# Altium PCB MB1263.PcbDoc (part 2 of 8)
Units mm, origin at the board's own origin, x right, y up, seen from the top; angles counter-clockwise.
Board outline 86 x 120 mm, 6 copper layers (Top Layer, Signal Layer 1, Signal Layer 2, Signal Layer 3, Signal Layer 4, Bottom Layer), stack 1.556 mm thick; 392 components, 421 nets, 1978 pads, 1444 vias.
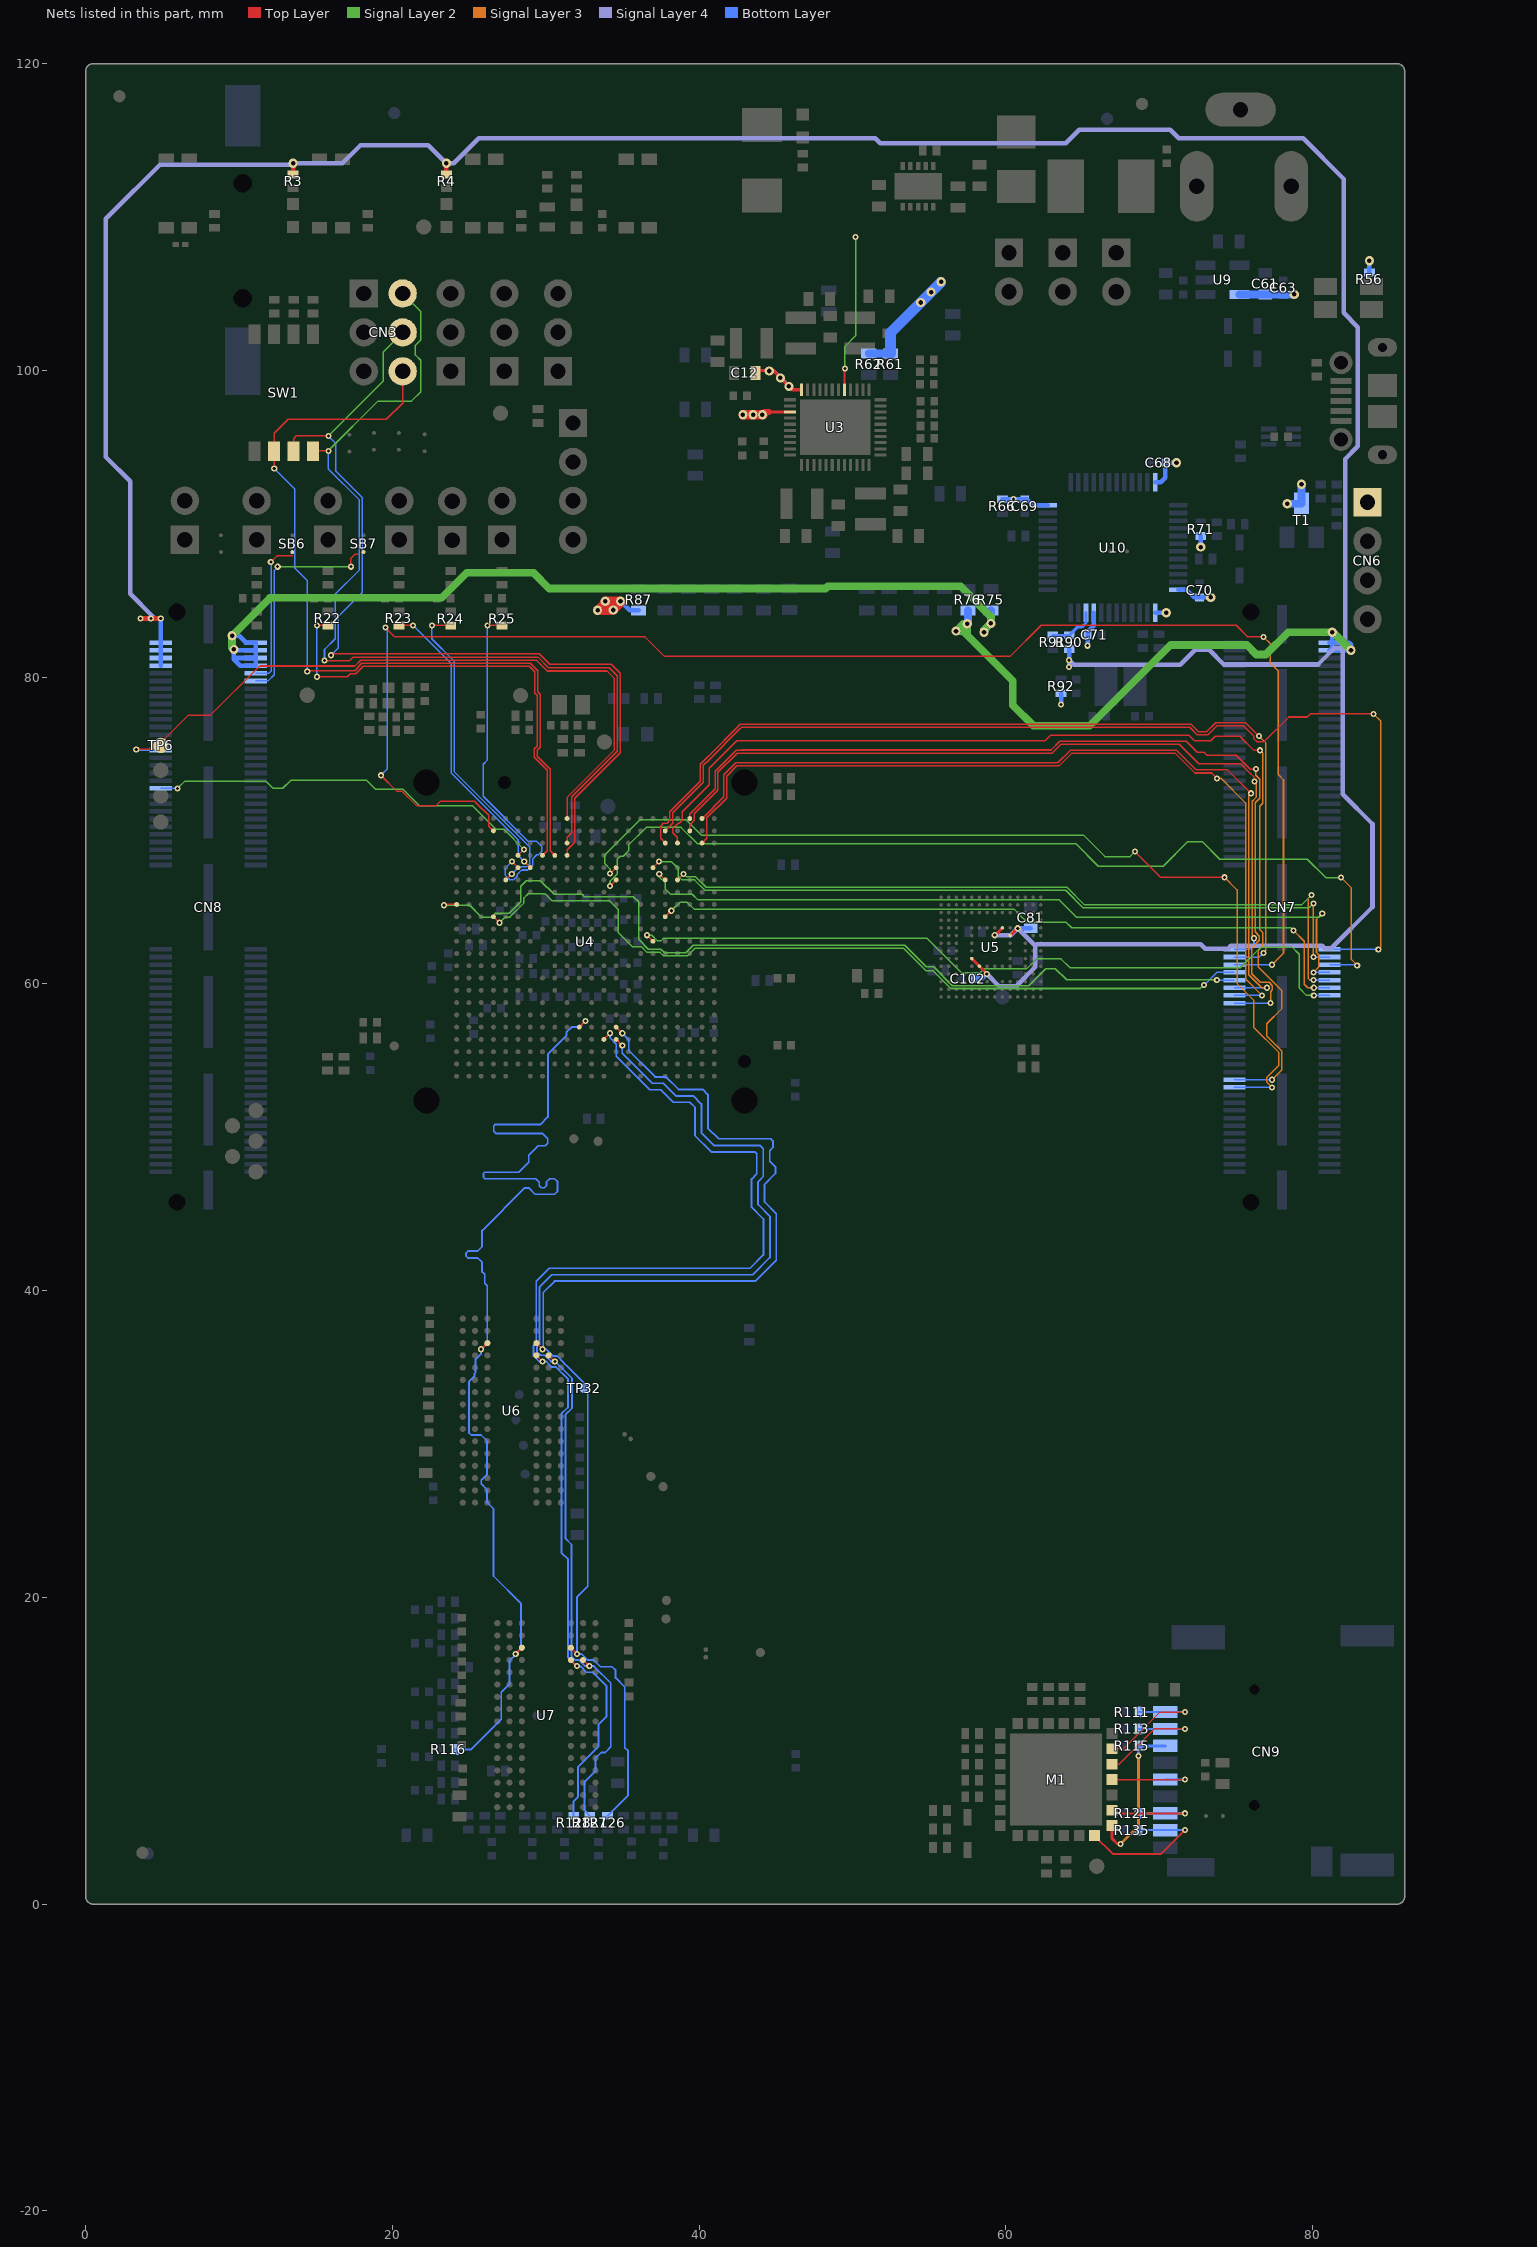
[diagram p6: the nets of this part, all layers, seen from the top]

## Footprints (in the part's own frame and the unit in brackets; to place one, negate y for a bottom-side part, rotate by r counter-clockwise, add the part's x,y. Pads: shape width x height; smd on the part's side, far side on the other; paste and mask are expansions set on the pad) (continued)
ICC_LFBGA448_18X18_STM32MP157BAA3_P080__SOCKET_IE_CS1627194MF [mm]
  round 0.32 smd mask+0.05: A1(-8.4,8.4) A2(-7.6,8.4) A3(-6.8,8.4) A4(-6,8.4) A5(-5.2,8.4) A6(-4.4,8.4) A7(-3.6,8.4) A8(-2.8,8.4) A9(-2,8.4) A10(-1.2,8.4) A11(-0.4,8.4) A12(0.4,8.4) A13(1.2,8.4) A14(2,8.4) A15(2.8,8.4) A16(3.6,8.4) A17(4.4,8.4) A18(5.2,8.4) A19(6,8.4) A20(6.8,8.4) A21(7.6,8.4) A22(8.4,8.4) AA1(-8.4,-7.6) AA2(-7.6,-7.6) AA3(-6.8,-7.6) AA4(-6,-7.6) AA5(-5.2,-7.6) AA6(-4.4,-7.6) AA7(-3.6,-7.6) AA8(-2.8,-7.6) AA9(-2,-7.6) AA10(-1.2,-7.6) AA11(-0.4,-7.6) AA12(0.4,-7.6) AA13(1.2,-7.6) AA14(2,-7.6) AA15(2.8,-7.6) AA16(3.6,-7.6) AA17(4.4,-7.6) AA18(5.2,-7.6) AA19(6,-7.6) AA20(6.8,-7.6) AA21(7.6,-7.6) AA22(8.4,-7.6) AB1(-8.4,-8.4) AB2(-7.6,-8.4) AB3(-6.8,-8.4) AB4(-6,-8.4) AB5(-5.2,-8.4) AB6(-4.4,-8.4) AB7(-3.6,-8.4) AB8(-2.8,-8.4) AB9(-2,-8.4) AB10(-1.2,-8.4) AB11(-0.4,-8.4) AB12(0.4,-8.4) AB13(1.2,-8.4) AB14(2,-8.4) AB15(2.8,-8.4) AB16(3.6,-8.4) AB17(4.4,-8.4) AB18(5.2,-8.4) AB19(6,-8.4) AB20(6.8,-8.4) AB21(7.6,-8.4) AB22(8.4,-8.4) B1(-8.4,7.6) B2(-7.6,7.6) B3(-6.8,7.6) B4(-6,7.6) B5(-5.2,7.6) B6(-4.4,7.6) B7(-3.6,7.6) B8(-2.8,7.6) B9(-2,7.6) B10(-1.2,7.6) B11(-0.4,7.6) B12(0.4,7.6) B13(1.2,7.6) B14(2,7.6) B15(2.8,7.6) B16(3.6,7.6) B17(4.4,7.6) B18(5.2,7.6) B19(6,7.6) B20(6.8,7.6) B21(7.6,7.6) B22(8.4,7.6) C1(-8.4,6.8) C2(-7.6,6.8) C3(-6.8,6.8) C4(-6,6.8) C5(-5.2,6.8) C6(-4.4,6.8) C7(-3.6,6.8) C8(-2.8,6.8) C9(-2,6.8) C10(-1.2,6.8) C11(-0.4,6.8) C12(0.4,6.8) C13(1.2,6.8) C14(2,6.8) C15(2.8,6.8) C16(3.6,6.8) C17(4.4,6.8) C18(5.2,6.8) C19(6,6.8) C20(6.8,6.8) C21(7.6,6.8) C22(8.4,6.8) D1(-8.4,6) D2(-7.6,6) D3(-6.8,6) D4(-6,6) D5(-5.2,6) D6(-4.4,6) D7(-3.6,6) D8(-2.8,6) D9(-2,6) D10(-1.2,6) D11(-0.4,6) D12(0.4,6) D13(1.2,6) D14(2,6) D15(2.8,6) D16(3.6,6) D17(4.4,6) D18(5.2,6) D19(6,6) D20(6.8,6) D21(7.6,6) D22(8.4,6) E1(-8.4,5.2) E2(-7.6,5.2) E3(-6.8,5.2) E4(-6,5.2) E5(-5.2,5.2) E6(-4.4,5.2) E7(-3.6,5.2) E8(-2.8,5.2) E9(-2,5.2) E10(-1.2,5.2) E11(-0.4,5.2) E12(0.4,5.2) E13(1.2,5.2) E14(2,5.2) E15(2.8,5.2) E16(3.6,5.2) E17(4.4,5.2) E18(5.2,5.2) E19(6,5.2) E20(6.8,5.2) E21(7.6,5.2) E22(8.4,5.2) F1(-8.4,4.4) F2(-7.6,4.4) F3(-6.8,4.4) F4(-6,4.4) F5(-5.2,4.4) F6(-4.4,4.4) F7(-3.6,4.4) F8(-2.8,4.4) F9(-2,4.4) F10(-1.2,4.4) F11(-0.4,4.4) F12(0.4,4.4) F13(1.2,4.4) F14(2,4.4) F15(2.8,4.4) F16(3.6,4.4) F17(4.4,4.4) F18(5.2,4.4) F19(6,4.4) F20(6.8,4.4) F21(7.6,4.4) G1(-8.4,3.6) G2(-7.6,3.6) G3(-6.8,3.6) G4(-6,3.6) G5(-5.2,3.6) G6(-4.4,3.6) G8(-2.8,3.6) G10(-1.2,3.6) G12(0.4,3.6) G14(2,3.6) G16(3.6,3.6) G17(4.4,3.6) G18(5.2,3.6) G19(6,3.6) G20(6.8,3.6) G21(7.6,3.6) G22(8.4,3.6) H1(-8.4,2.8) H2(-7.6,2.8) H3(-6.8,2.8) H4(-6,2.8) H5(-5.2,2.8) H6(-4.4,2.8) H7(-3.6,2.8) H9(-2,2.8) H11(-0.4,2.8) H13(1.2,2.8) H15(2.8,2.8) H17(4.4,2.8) H18(5.2,2.8) H19(6,2.8) H20(6.8,2.8) H21(7.6,2.8) H22(8.4,2.8) J1(-8.4,2) J2(-7.6,2) J3(-6.8,2) J4(-6,2) J5(-5.2,2) J6(-4.4,2) J8(-2.8,2) J9(-2,2) J10(-1.2,2) J11(-0.4,2) J12(0.4,2) J13(1.2,2) J14(2,2) J16(3.6,2) J17(4.4,2) J18(5.2,2) J19(6,2) J20(6.8,2) J21(7.6,2) K1(-8.4,1.2) K2(-7.6,1.2) K3(-6.8,1.2) K4(-6,1.2) K5(-5.2,1.2) K6(-4.4,1.2) K7(-3.6,1.2) K9(-2,1.2) K10(-1.2,1.2) K11(-0.4,1.2) K12(0.4,1.2) K13(1.2,1.2) K14(2,1.2) K15(2.8,1.2) K17(4.4,1.2) K18(5.2,1.2) K19(6,1.2) K20(6.8,1.2) K21(7.6,1.2) K22(8.4,1.2) L1(-8.4,0.4) L2(-7.6,0.4) L3(-6.8,0.4) L4(-6,0.4) L5(-5.2,0.4) L6(-4.4,0.4) L8(-2.8,0.4) L9(-2,0.4) L10(-1.2,0.4) L11(-0.4,0.4) L12(0.4,0.4) L13(1.2,0.4) L14(2,0.4) L16(3.6,0.4) L17(4.4,0.4) L18(5.2,0.4) L19(6,0.4) L20(6.8,0.4) L21(7.6,0.4) L22(8.4,0.4) M1(-8.4,-0.4) M2(-7.6,-0.4) M3(-6.8,-0.4) M4(-6,-0.4) M5(-5.2,-0.4) M6(-4.4,-0.4) M7(-3.6,-0.4) M9(-2,-0.4) M10(-1.2,-0.4) M11(-0.4,-0.4) M12(0.4,-0.4) M13(1.2,-0.4) M14(2,-0.4) M15(2.8,-0.4) M17(4.4,-0.4) M18(5.2,-0.4) M19(6,-0.4) M20(6.8,-0.4) M21(7.6,-0.4) M22(8.4,-0.4) N1(-8.4,-1.2) N2(-7.6,-1.2) N3(-6.8,-1.2) N4(-6,-1.2) N5(-5.2,-1.2) N6(-4.4,-1.2) N8(-2.8,-1.2) N9(-2,-1.2) N10(-1.2,-1.2) N11(-0.4,-1.2) N12(0.4,-1.2) N13(1.2,-1.2) N14(2,-1.2) N16(3.6,-1.2) N17(4.4,-1.2) N18(5.2,-1.2) N19(6,-1.2) N20(6.8,-1.2) N21(7.6,-1.2) N22(8.4,-1.2) P1(-8.4,-2) P2(-7.6,-2) P3(-6.8,-2) P4(-6,-2) P5(-5.2,-2) P6(-4.4,-2) P7(-3.6,-2) P9(-2,-2) P10(-1.2,-2) P11(-0.4,-2) P12(0.4,-2) P13(1.2,-2) P14(2,-2) P15(2.8,-2) P17(4.4,-2) P18(5.2,-2) P19(6,-2) P20(6.8,-2) P21(7.6,-2) R1(-8.4,-2.8) R2(-7.6,-2.8) R3(-6.8,-2.8) R4(-6,-2.8) R5(-5.2,-2.8) R6(-4.4,-2.8) R8(-2.8,-2.8) R10(-1.2,-2.8) R12(0.4,-2.8) R14(2,-2.8) R16(3.6,-2.8) R17(4.4,-2.8) R18(5.2,-2.8) R19(6,-2.8) R20(6.8,-2.8) R21(7.6,-2.8) R22(8.4,-2.8) T1(-8.4,-3.6) T2(-7.6,-3.6) T3(-6.8,-3.6) T4(-6,-3.6) T5(-5.2,-3.6) T6(-4.4,-3.6) T7(-3.6,-3.6) T9(-2,-3.6) T11(-0.4,-3.6) T13(1.2,-3.6) T15(2.8,-3.6) T17(4.4,-3.6) T18(5.2,-3.6) T19(6,-3.6) T20(6.8,-3.6) T21(7.6,-3.6) T22(8.4,-3.6) U1(-8.4,-4.4) U2(-7.6,-4.4) U3(-6.8,-4.4) U4(-6,-4.4) U5(-5.2,-4.4) U6(-4.4,-4.4) U7(-3.6,-4.4) U8(-2.8,-4.4) U9(-2,-4.4) U10(-1.2,-4.4) U11(-0.4,-4.4) U12(0.4,-4.4) U13(1.2,-4.4) U14(2,-4.4) U15(2.8,-4.4) U16(3.6,-4.4) U17(4.4,-4.4) U18(5.2,-4.4) U19(6,-4.4) U20(6.8,-4.4) U21(7.6,-4.4) V1(-8.4,-5.2) V2(-7.6,-5.2) V3(-6.8,-5.2) V4(-6,-5.2) V5(-5.2,-5.2) V6(-4.4,-5.2) V7(-3.6,-5.2) V8(-2.8,-5.2) V9(-2,-5.2) V10(-1.2,-5.2) V11(-0.4,-5.2) V12(0.4,-5.2) V13(1.2,-5.2) V14(2,-5.2) V15(2.8,-5.2) V16(3.6,-5.2) V17(4.4,-5.2) V18(5.2,-5.2) V19(6,-5.2) V20(6.8,-5.2) V21(7.6,-5.2) V22(8.4,-5.2) W1(-8.4,-6) W2(-7.6,-6) W3(-6.8,-6) W4(-6,-6) W5(-5.2,-6) W6(-4.4,-6) W7(-3.6,-6) W8(-2.8,-6) W9(-2,-6) W10(-1.2,-6) W11(-0.4,-6) W12(0.4,-6) W13(1.2,-6) W14(2,-6) W15(2.8,-6) W16(3.6,-6) W17(4.4,-6) W18(5.2,-6) W19(6,-6) W20(6.8,-6) W21(7.6,-6) W22(8.4,-6) Y1(-8.4,-6.8) Y2(-7.6,-6.8) Y3(-6.8,-6.8) Y4(-6,-6.8) Y5(-5.2,-6.8) Y6(-4.4,-6.8) Y7(-3.6,-6.8) Y8(-2.8,-6.8) Y9(-2,-6.8) Y10(-1.2,-6.8) Y11(-0.4,-6.8) Y12(0.4,-6.8) Y13(1.2,-6.8) Y14(2,-6.8) Y15(2.8,-6.8) Y16(3.6,-6.8) Y17(4.4,-6.8) Y18(5.2,-6.8) Y19(6,-6.8) Y20(6.8,-6.8) Y21(7.6,-6.8) Y22(8.4,-6.8)
  round 0.5 hole 1.7 unplated mask+0.05: NPTH1(-10.737,10.362) NPTH2(9.987,10.362) NPTH3(-10.737,-10.362) NPTH4(9.987,-10.362)
  round 0.5 hole 0.85 unplated mask+0.05: NPTH5(-10.737,-5.282) NPTH6(7.447,10.362)
  silkscreen extent -12.12,-11.61 11.24,11.75, body extent -13.14,-12.76 12.39,12.76, height 10.18
ICC_LQFP48_7X7_P050 [mm]
  rect 0.3x1.2 smd mask+0.05: 1(-2.75,-4.25) 2(-2.25,-4.25) 3(-1.75,-4.25) 4(-1.25,-4.25) 5(-0.75,-4.25) 6(-0.25,-4.25) 7(0.25,-4.25) 8(0.75,-4.25) 9(1.25,-4.25) 10(1.75,-4.25) 11(2.25,-4.25) 12(2.75,-4.25) 25(2.75,4.25) 26(2.25,4.25) 27(1.75,4.25) 28(1.25,4.25) 29(0.75,4.25) 30(0.25,4.25) 31(-0.25,4.25) 32(-0.75,4.25) 33(-1.25,4.25) 34(-1.75,4.25) 35(-2.25,4.25) 36(-2.75,4.25)
  rect 1.2x0.3 smd mask+0.05: 13(4.25,-2.75) 14(4.25,-2.25) 15(4.25,-1.75) 16(4.25,-1.25) 17(4.25,-0.75) 18(4.25,-0.25) 19(4.25,0.25) 20(4.25,0.75) 21(4.25,1.25) 22(4.25,1.75) 23(4.25,2.25) 24(4.25,2.75) 37(-4.25,2.75) 38(-4.25,2.25) 39(-4.25,1.75) 40(-4.25,1.25) 41(-4.25,0.75) 42(-4.25,0.25) 43(-4.25,-0.25) 44(-4.25,-0.75) 45(-4.25,-1.25) 46(-4.25,-1.75) 47(-4.25,-2.25) 48(-4.25,-2.75)
  silkscreen extent -3.52,-3.52 3.52,3.52, body extent -4.5,-4.5 4.5,4.5, height 1.6
ICC_P-WFBGA153_13X11P5_P050 [mm]
  round 0.23 smd mask+0.05: A1(-3.25,-3.25) A2(-3.25,-2.75) A3(-3.25,-2.25) A4(-3.25,-1.75) A5(-3.25,-1.25) A6(-3.25,-0.75) A7(-3.25,-0.25) A8(-3.25,0.25) A9(-3.25,0.75) A10(-3.25,1.25) A11(-3.25,1.75) A12(-3.25,2.25) A13(-3.25,2.75) A14(-3.25,3.25) B1(-2.75,-3.25) B2(-2.75,-2.75) B3(-2.75,-2.25) B4(-2.75,-1.75) B5(-2.75,-1.25) B6(-2.75,-0.75) B7(-2.75,-0.25) B8(-2.75,0.25) B9(-2.75,0.75) B10(-2.75,1.25) B11(-2.75,1.75) B12(-2.75,2.25) B13(-2.75,2.75) B14(-2.75,3.25) C1(-2.25,-3.25) C2(-2.25,-2.75) C3(-2.25,-2.25) C4(-2.25,-1.75) C5(-2.25,-1.25) C6(-2.25,-0.75) C7(-2.25,-0.25) C8(-2.25,0.25) C9(-2.25,0.75) C10(-2.25,1.25) C11(-2.25,1.75) C12(-2.25,2.25) C13(-2.25,2.75) C14(-2.25,3.25) D1(-1.75,-3.25) D2(-1.75,-2.75) D3(-1.75,-2.25) D4(-1.75,-1.75) D12(-1.75,2.25) D13(-1.75,2.75) D14(-1.75,3.25) E1(-1.25,-3.25) E2(-1.25,-2.75) E3(-1.25,-2.25) E5(-1.25,-1.25) E6(-1.25,-0.75) E7(-1.25,-0.25) E8(-1.25,0.25) E9(-1.25,0.75) E10(-1.25,1.25) E12(-1.25,2.25) E13(-1.25,2.75) E14(-1.25,3.25) F1(-0.75,-3.25) F2(-0.75,-2.75) F3(-0.75,-2.25) F5(-0.75,-1.25) F10(-0.75,1.25) F12(-0.75,2.25) F13(-0.75,2.75) F14(-0.75,3.25) G1(-0.25,-3.25) G2(-0.25,-2.75) G3(-0.25,-2.25) G5(-0.25,-1.25) G10(-0.25,1.25) G12(-0.25,2.25) G13(-0.25,2.75) G14(-0.25,3.25) H1(0.25,-3.25) H2(0.25,-2.75) H3(0.25,-2.25) H5(0.25,-1.25) H10(0.25,1.25) H12(0.25,2.25) H13(0.25,2.75) H14(0.25,3.25) J1(0.75,-3.25) J2(0.75,-2.75) J3(0.75,-2.25) J5(0.75,-1.25) J10(0.75,1.25) J12(0.75,2.25) J13(0.75,2.75) J14(0.75,3.25) K1(1.25,-3.25) K2(1.25,-2.75) K3(1.25,-2.25) K5(1.25,-1.25) K6(1.25,-0.75) K7(1.25,-0.25) K8(1.25,0.25) K9(1.25,0.75) K10(1.25,1.25) K12(1.25,2.25) K13(1.25,2.75) K14(1.25,3.25) L1(1.75,-3.25) L2(1.75,-2.75) L3(1.75,-2.25) L12(1.75,2.25) L13(1.75,2.75) L14(1.75,3.25) M1(2.25,-3.25) M2(2.25,-2.75) M3(2.25,-2.25) M4(2.25,-1.75) M5(2.25,-1.25) M6(2.25,-0.75) M7(2.25,-0.25) M8(2.25,0.25) M9(2.25,0.75) M10(2.25,1.25) M11(2.25,1.75) M12(2.25,2.25) M13(2.25,2.75) M14(2.25,3.25) N1(2.75,-3.25) N2(2.75,-2.75) N3(2.75,-2.25) N4(2.75,-1.75) N5(2.75,-1.25) N6(2.75,-0.75) N7(2.75,-0.25) N8(2.75,0.25) N9(2.75,0.75) N10(2.75,1.25) N11(2.75,1.75) N12(2.75,2.25) N13(2.75,2.75) N14(2.75,3.25) P1(3.25,-3.25) P2(3.25,-2.75) P3(3.25,-2.25) P4(3.25,-1.75) P5(3.25,-1.25) P6(3.25,-0.75) P7(3.25,-0.25) P8(3.25,0.25) P9(3.25,0.75) P10(3.25,1.25) P11(3.25,1.75) P12(3.25,2.25) P13(3.25,2.75) P14(3.25,3.25)
  silkscreen extent -6.78,-6.02 6.63,5.87, body extent -6.55,-5.8 6.55,5.8, height 1
ICC_WFQFN44-EPAD_5X6_P040 [mm]
  rect 0.8x0.2 smd mask+0.05: 1(-2.45,2.2) 2(-2.45,1.8) 3(-2.45,1.4) 4(-2.45,1) 5(-2.45,0.6) 6(-2.45,0.2) 7(-2.45,-0.2) 8(-2.45,-0.6) 9(-2.45,-1) 10(-2.45,-1.4) 11(-2.45,-1.8) 12(-2.45,-2.2) 23(2.45,-2.2) 24(2.45,-1.8) 25(2.45,-1.4) 26(2.45,-1) 27(2.45,-0.6) 28(2.45,-0.2) 29(2.45,0.2) 30(2.45,0.6) 31(2.45,1) 32(2.45,1.4) 33(2.45,1.8) 34(2.45,2.2)
  rect 0.2x0.8 smd mask+0.05: 13(-1.8,-2.95) 14(-1.4,-2.95) 15(-1,-2.95) 16(-0.6,-2.95) 17(-0.2,-2.95) 18(0.2,-2.95) 19(0.6,-2.95) 20(1,-2.95) 21(1.4,-2.95) 22(1.8,-2.95) 35(1.8,2.95) 36(1.4,2.95) 37(1,2.95) 38(0.6,2.95) 39(0.2,2.95) 40(-0.2,2.95) 41(-0.6,2.95) 42(-1,2.95) 43(-1.4,2.95) 44(-1.8,2.95)
  rect 3.6x4.6 smd paste-1.8 mask+0.05: ep(0,0)
  silkscreen extent -2.5,-3 2.5,3, body extent -2.5,-3 2.5,3, height 0.81
IND_2520_TOKO_DFE252012P [mm]
  rect 0.8x2 smd mask+0.05: 1(-1,0) 2(1,0)
  silkscreen extent -1.35,-1.12 1.35,1.12, body extent -1.35,-1.1 1.35,1.1, height 2
L0603 [mm]
  rect 0.8x0.95 smd mask+0.05: 1(-0.8,0) 2(0.8,0)
  silkscreen extent -1.33,-0.6 1.33,0.6, body extent -0.87,-0.47 0.87,0.47, height 0.95
LED_0603_GREEN [mm]
  rect 0.8x0.8 smd mask+0.05: 1(-0.75,0) 2(0.75,0)
  silkscreen extent -0.25,-0.4 1.25,0.4, body extent -0.8,-0.4 0.8,0.4, height 0.6
LED_0603_ORANGE_H0P4 [mm]
  rect 0.8x0.8 smd mask+0.05: 1(-0.75,0) 2(0.75,0)
  silkscreen extent -0.25,-0.4 1.25,0.4, body extent -0.8,-0.4 0.79,0.4, height 0.4
LED_0603_RED [mm]
  rect 0.8x0.8 smd mask+0.05: 1(-0.75,0) 2(0.75,0)
  silkscreen extent -0.25,-0.4 1.25,0.4, body extent -0.8,-0.4 0.8,0.4, height 0.6
LED_0603_SMD-B_BLUE_H0P4 [mm]
  rect 0.6x1 smd mask+0.05: 1(-0.65,0) 2(0.65,0)
  silkscreen extent -0.23,-0.45 1.07,0.45, body extent -0.85,-0.45 0.85,0.45, height 0.5
LED_BI-GR_HSMF-A201-A00J1 [mm]
  rect 1.1x1.5 smd mask+0.05: 1(-0.75,-1.5) 2(-0.75,1.5) 3(0.75,1.5) 4(0.75,-1.5)
  silkscreen extent -1.65,-1.85 1.65,1.85, body extent -1.5,-1.85 1.5,1.85, height 2.1
LINK200 [mm]
  rect 0.2x0.35 on Mid4 mask+0.05: 1(0,-0.225) 2(0,0.225)
MIRE_PLACE_SMD_0P8MM [mm]
  round 0.8 smd paste-10 mask+0.2: 1(0,0)
  Top Layer keep-out circle w0.01: c0,0 r0.804
MOD_SD-CARD_8X8_MB1256 [mm] "MB1256"
  rect 0.7x0.7 smd mask+0.05: 1(-3.65,3) 2(-3.65,2) 3(-3.65,1) 4(-3.65,0) 5(-3.65,-1) 6(-3.65,-2) 7(-3.65,-3) 8(-2.5,-3.65) 9(-1.5,-3.65) 10(-0.5,-3.65) 11(0.5,-3.65) 12(1.5,-3.65) 13(2.5,-3.65) 14(3.65,-3) 15(3.65,-2) 16(3.65,-1) 17(3.65,0) 18(3.65,1) 19(3.65,2) 20(3.65,3) 21(2.5,3.65) 22(1.5,3.65) 23(0.5,3.65) 24(-0.5,3.65) 25(-1.5,3.65) 26(-2.5,3.65)
  rect 6x6 smd mask+0.05: 27(0,0)
  silkscreen extent -4,-4 4,4, body extent -4,-4 4,4, height 1.4
NPN_SOT23 [mm]
  rect 1x1.4 smd mask+0.05: 1(-0.95,-1.1) 2(0.95,-1.1) 3(0,1.1)
  silkscreen extent -1.63,-0.82 1.63,0.82, body extent -1.56,-1.25 1.56,1.25, height 1.1
PTC_BEL-FUSE_1812_0ZCG0260FF2C [mm]
  rect 2.4x3.5 smd mask+0.05: 1(-2.3,0) 2(2.3,0)
  silkscreen extent -1,-1.73 1,1.73, body extent -2.36,-1.71 2.36,1.71, height 1.2
R0402 [mm]
  rect 0.51x0.7 smd mask+0.05: 1(-0.45,0) 2(0.45,0)
  silkscreen extent 0,-0.3 0,0.3, body extent -0.52,-0.3 0.52,0.3, height 0.4
R0603 [mm]
  rect 0.64x1 smd mask+0.05: 1(-0.7,0) 2(0.7,0)
  silkscreen extent -1.05,-0.58 1.05,0.58, body extent -0.9,-0.5 0.9,0.5, height 0.56
REG_SOT23-5L [mm]
  rect 0.6x1.3 smd mask+0.05: 1(-0.95,-1.1) 2(0,-1.1) 3(0.95,-1.1) 4(0.95,1.1) 5(-0.95,1.1)
  silkscreen extent -1.6,-0.95 1.6,0.97, body extent -1.52,-1.25 1.52,1.25, height 1.1
SOLDER-BRIDGE_R0603-0R [mil]
  round 10 smd paste-393.7: 1(-19.68,0) 2(23.62,0)
  Top Layer region: -5.91,19.68 13.78,0 -5.91,-19.69 47.24,-19.69 47.24,19.68 -5.91,19.68
  Top Layer region: -47.24,-19.69 -47.24,19.68 -15.75,19.68 3.94,0 -15.75,-19.69 -47.24,-19.69
  silkscreen extent -50,-23 50,23, body extent -36,-20 36,20, height 22
SWI_CTS_CTS218-4LP [mm] "GULL WING TERMINAL"
  rect 0.76x1.27 smd mask+0.05: 1(-1.905,-3.81) 2(-0.635,-3.81) 3(0.635,-3.81) 4(1.905,-3.81) 5(1.905,3.81) 6(0.635,3.81) 7(-0.635,3.81) 8(-1.905,3.81)
  silkscreen extent -3.13,-3.05 3.13,3.05, body extent -3.18,-4.32 3.18,4.32, height 2.85
SWI_JIUBABA_C-TS-02H-2-5-B-V-T_R_BLUE [mm] "BLUE"
  rect 0.75x1 smd mask+0.05: 1(-2.225,0.75) 2(2.225,0.75) 3(-2.225,-0.75) 4(2.225,-0.75)
  silkscreen extent -1.85,-1.6 1.85,1.6, body extent -2.45,-1.6 2.45,1.6, height 2.6
SWI_JIUBABA_C-TS-02H-2-5-K-V-T_R_BLACK [mm] "BLACK"
  rect 0.75x1 smd mask+0.05: 1(-2.225,0.75) 2(2.225,0.75) 3(-2.225,-0.75) 4(2.225,-0.75)
  silkscreen extent -1.85,-1.6 1.85,1.6, body extent -2.45,-1.6 2.45,1.6, height 2.6
TP_SMD_0-3MM [mm]
  round 0.3 smd paste-10 mask+0.05: 1(0,0)
  silkscreen extent -0.3,-0.3 0.3,0.3
TP_SMD_0-6MM [mm]
  round 0.6 smd paste-10 mask+0.05: 1(0,0)
  silkscreen extent -0.5,-0.5 0.5,0.5
TP_SMD_1MM [mm]
  round 1 smd paste-10 mask+0.05: 1(0,0)
  silkscreen extent -0.7,-0.7 0.7,0.7

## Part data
B1: "TS-02H SMD Light Touch Switch black", Manuf_1=Jiubaba, Manuf_Part_1="C-TS-02H-2.5-K-V-T/R BLACK"
B2 B3 B4: "TS-02H SMD Light Touch Switch blue", Manuf_1=Jiubaba, Manuf_Part_1="C-TS-02H-2.5-K-V-T/R BLUE"
BT1: "Battery  holder xcfbattery XCF-12", Manuf_1=xcfbattery, Manuf_Part_1=XCF-12
C1: library part Cap_220uF_POL_10%_TAJA, "Polarized Capacitor,220uF,10V,10%,AVX", Manuf_1=AVX, Manuf_Part_1=TAJC227K010R
C2 C18 C28 C29 C30 C31 C32 C34 C38 C40 C41 C44 C45 C46 C47 C49 C50 C51 C52 C53 C54 C58 C63 C64 C65 C66 C68 C69 C70 C71 C72 C75 C92 C97 C102 C113 C115 C116 C117 C118 C119 C120 C121 C123 C124 C125 C126 C127 C128 C129 C131 C132 C135 C136 C137 C138 C139 C140: library part Cap_100nF_X7R_10%_0402, "Capacitor,100nF,16V,X7R,10%,0402,YAGEO", Manuf_1=YAGEO, Manuf_Part_1=CC0402KRX7R7BB104
C3 C4 C55 C61 C62 C76: library part Cap_1uF_X5R_10%_0603, "Capacitor,1uF,16V,X5R,10%,0603,YAGEO", Manuf_1=YAGEO, Manuf_Part_1=CC0603KRX5R7BB105
C5 C300: library part Cap_10nF_X7R_10%_0402, "Capacitor,10nF,16V,X7R,10%,0402,YAGEO", Manuf_1=YAGEO, Manuf_Part_1=CC0402KRX7R7BB103
C6 C7 C12 C26 C27 C133 C134: library part Cap_22uF_X5R_20%_0603_MURATA, "Capacitor MLCC 22µF 20% 6,3V 7,5µF@3,3V ESR=4mohm@100kHz  Z=5mohm@2MHz X5R 0603", Manuf_1=MURATA, Manuf_Part_1=GRM188R60J226MEA0J
C8 C9 C10 C22 C23 C24 C25: library part Cap_10uF_X5R_10%_0603_MURATA, "Capacitor MLCC 10µF 10% 10V 2,5µF@5,5V Z=5mohm@2MHz X5R 0603", Manuf_1=MURATA, Manuf_Part_1=GRM188R61A106KE69D
C11 C13 C14 C15 C17 C20 C21: library part Cap_4.7uF_X5R_20%_6V3_0402, "Capacitor MLCC 4,7µF 20% 6,3V 1,9uF@3,3V X5R 0402", Manuf_1=MURATA, Manuf_Part_1=GRM155R60J475ME47
C16 C19 C42 C43 C67 C77 C78 C79 C80 C82 C83 C84 C85 C86 C87 C88 C89 C90 C91 C93 C94 C96 C98 C99 C100 C101 C103 C104 C105 C106 C109 C110 C111 C112 C114: library part Cap_1uF_X5R_10%_6V3_0402, "Capacitor MLCC 1µF 10% 6,3V 0,4uF@3,3V X5R 0402 MURATA", Manuf_1=MURATA, Manuf_Part_1=GRM155R61E105KA12
C33 C35 C36 C37: library part Cap_6.8pF_NPO_0402, "Capacitor, MLCC, 6.8pF, 50V, NPO, +-0.25pF, 0402, T=0.5mm", Manuf_1=YAGEO, Manuf_Part_1=CC0402CRNPO9BN6R8, Package=C0402
C39 C81 C95: library part Cap_2.2uF_X5R_10%_0603, "Capacitor,2.2uF,10V, X5R,10%,0603,YAGEO", Manuf_1=YAGEO, Manuf_2=KEMET, Manuf_Part_1=CC0603KRX5R6BB225, Manuf_Part_2=C0603C225K8PACTU
C48 C59 C122 C130: library part Cap_10uF_X5R_10%_0603, "Capacitor,10uF,6.3V,X5R,10%,0603,YAGEO", Manuf_1=YAGEO, Manuf_Part_1=CC0603KRX5R5BB106
C56: library part Cap_100pF_NPO_5%_0402, "Capacitor,100pF,50V,NPO,5%,0402,YAGEO", Manuf_1=YAGEO, Manuf_Part_1=CC0402JRNPO9BN101
C57: library part Cap_4.7uF_X5R_20%_0603_16V_MURATA, "Capacitor MLCC 4,7uF 20% 16V 3uF@5V ESR=6mohm@100kHz  Z=20mohm@2MHz X5R 0603", Manuf_1=MURATA, Manuf_Part_1=GRM188R61C475MAAJ
C60: library part Cap_10nF_X7R_10%_0603, "Capacitor,10nF,50V,X7R,10%,0603,YAGEO", Manuf_1=YAGEO, Manuf_Part_1=CC0603KRX7R9BB103
C73 C74: library part Cap_10pF_NPO_5%_0402, "Capacitor,10pF,50V,NPO,5%,0402,YAGEO", Manuf_1=YAGEO, Manuf_Part_1=CC0402JRNPO9BN100
C107 C108: library part Cap_1nF_X7R_10%_0402, "Capacitor,1nF,16V,X7R,10%,0402,YAGEO", Manuf_1=YAGEO, Manuf_Part_1=CC0402KRX7R7BB102
CN1: library part CONN_Power_DC10B, "DC Power Jack 2.5mm 5A Right Angle through hole", Manuf_1=CLIFF, Manuf_Part_1=DC-10B
CN2: library part "Header 2 pins", "Header 2 pins", Manuf_1=SAMTEC, Manuf_2=KONTEC, Manuf_Part_1=TSW-102-07-x-S, Manuf_Part_2=4711955140470
CN3: library part MCD-00233, "Header, 3x2, 2,54mm, VR, TH, Height 5.84mm/2.54mm", Manufacturer=SAMTEC, Manufacturer_Part_Number=TSW-103-07-x-D
CN4: "USB-MICRO-B, 1050170001, SMT, MOLEX", Manuf_1=MOLEX
CN5 CN6: library part "Header 4", "Header, 4-Pin", Manuf_1=Samtec, Manuf_Part_1=TSW-104-07-x-S
CN7 CN8: "Samtec connector QTH 120p", Manuf_1=SAMTEC
CN9: library part microSD-PJS008-2003, "Memory Card Connectors MicroSD Card Conn Revrs Mnt Push-Push", Manuf_1=YAMAICHI
D1: library part SMAJ5.0A-TR, "Transil unidirectional diode Vrm=5.0V, Vbr=6.4V(10mA), Vcl=13.4V(174A), SMA", Manuf_1=STM
D2 D3 D4 D5: Manuf_1=STM
F1: library part 0ZCG0260FF2C, "SMD, PTC resettable fuse, IH:2.6A, IT:5A, Vdc_max:8V, Rmax:47mohm, BELFUSE", Manuf_1=BELFUSE
JP1 JP2 JP6 JP7 JP8 JP9 JP10 JP11: library part TSW-102-07-x-S, "Connector jumper 1 position", Manuf_1=SAMTEC, Manuf_2=KONTEC, Manuf_Part_2=4711955140470
JP3 JP4 JP5: library part "Header 3", "Header, 3-Pin", Manuf_1=Samtec, Manuf_Part_1=TSW-103-07-F-S
L1 L2 L3 L4 L5: library part IND_1uH_42mohm_3.2A, "SMD power inductor. 1µH, 3,2A, 42mohm, 2,5x2,0x1,2mm", Manuf_1=Murata, Manuf_Part_1=DFE252012P-1R0M{}P2
LD1 LD3: "LED, Green, 0603", Manuf_1=EVERLIGHT, Manuf_Part_1=19-213SYGC/S530-E2/TR8
LD2: "LED, Red, 0603", Manuf_1=EVERLIGHT, Manuf_Part_1=19-213-R6C-AP1Q2B/3T
LD4: "LED, Orange, 0603", Manuf_1=EVERLIGHT, Manuf_Part_1=19-217/S2C-AM2N2VY/3T, Package="LED 0603"
LD5: "LED Blue, 0603 SMD, Forward Voltage Min=2,8V, Max=3,1V", Manuf_1=EVERLIGHT, Manuf_Part_1=19-217-BHC-ZL1M2RY-3T
LD6: "Bicolor Led", Manuf_1="Avago Technologies", Manuf_2=everluck, Manuf_Part_1=HSMF-A201-A00J1, Manuf_Part_2=LE-RGW35280
LE1: library part "IND_4.7uH 600mohm_80mA_0603", "IND 4.7µH 20% 80mA 600mhom 0603", Manuf_1=MURATA, Manuf_Part_1=LQM18FN4R7M00D
LNK1 LNK2: "link 0.2mm"
M1: "SDcard3.0 dual voltage level  translator", Manuf_1=STM, Manuf_Part_1=MB1256
R1: library part Res_39_1%_0402, "Resistor,39R,0402,1%,YAGEO", Manuf_1=YAGEO, Manuf_Part_1=RC0402FR-0739RL
R2 R4 R57 R58: library part Res_330_1%_0402, "Resistor,330R,0402,1%,YAGEO", Manuf_1=YAGEO, Manuf_Part_1=RC0402FR-07330RL
R3 R11 R12 R13 R66 R303: library part Res_1K_1%_0402, "Resistor,1K,0402,1%,YAGEO", Manuf_1=YAGEO, Manuf_Part_1=RC0402FR-071KL
R5 R6: "Resistor,680R,0402,1%,1/16W", Manuf_1=YAGEO, Manuf_Part_1=RC0402FR-07680RL, Package=R0402
R7 R50 R59 R60 R61 R62 R63 R64 R68 R72 R75 R76 R77 R78 R79 R80 R81 R82 R83 R84 R85 R86 R87: library part Res_0_ULO_0603, "Resistor,0R,0603,ULO,ROHM", Manuf_1=ROHM, Manuf_Part_1=PMR03EZPJ000
R8 R33 R37 R38 R39 R40 R41 R43 R44 R46 R47 R48 R49 R52 R88 R89 R97 R100 R103 R108 R111 R113 R115 R121 R135 R302 R900 R901: library part Res_10K_1%_0402, "Resistor,10K,0402,1%,YAGEO", Manuf_1=YAGEO, Manuf_Part_1=RC0402FR-0710KL
R9 R10 R67 R118: library part Res_100_1%_0402, "Resistor,100R,0402,1%,YAGEO", Manuf_1=YAGEO, Manuf_Part_1=RC0402FR-07100RL
R14 R73 R74 R92: library part Res_100K_1%_0402, "Resistor,100K,0402,1%,YAGEO", Manuf_1=YAGEO, Manuf_Part_1=RC0402FR-07100KL, Manuf_Part_2=RT0402FRE07100KL
R15 R16 R17 R18 R19 R20 R21 R22 R23 R24 R25 R26 R27 R28 R29 R42 R45 R54 R56 R71 R94 R95 R96 R98 R99 R101: library part Res_0_5%_0402, "Resistor,0R,0402,5%,YAGEO", Manuf_1=YAGEO, Manuf_Part_1=RC0402JR-070RL
R30 R31 R34 R35 R51 R53 R93: library part Res_1K5_1%_0402, "Resistor,1K5,0402,1%,YAGEO", Manuf_1=YAGEO, Manuf_Part_1=RC0402FR-071K5L
R32: library part Res_3K_1%_0402, "Resistor,3K,0402,1%,YAGEO", Manuf_1=YAGEO, Manuf_Part_1=RC0402FR-073KL
R36 R55 R102: library part Res_240_1%_0402, "Resistor,240R,0402,1%,YAGEO", Manuf_1=YAGEO, Manuf_Part_1=RC0402FR-07240RL
R65: library part Res_36K_1%_0402, "Resistor,36K,0402,1%,YAGEO", Manuf_1=YAGEO, Manuf_Part_1=RC0402FR-0736KL
R69 R90 R91: library part Res_4K7_1%_0402, "Resistor,4K7,0402,1%,YAGEO", Manuf_1=YAGEO, Manuf_Part_1=RC0402FR-074K7L, Manuf_Part_2=RT0402FRE074K7L
R70: library part Res_2K7_1%_0402, "Resistor,2K7,0402,1%,YAGEO", Manuf_1=YAGEO, Manuf_Part_1=RC0402FR-072K7L
R104 R105 R106 R107 R109 R110 R112 R114 R116 R117 R119 R120 R122 R123 R124 R125 R126 R127 R128 R129 R130 R131 R132 R133 R134: library part Res_56_1%_0402, "Resistor,56R,0402,1%,YAGEO", Manuf_1=YAGEO, Manuf_Part_1=RC0402FR-0756RL
R300: library part Res_10R_1%_0402, "Resistor,10R,0402,1%,1/16W", Manuf_1=YAGEO, Manuf_Part_1=RC0402FR-0710RL
SB1 SB4 SB5 SB6 SB7 SB8 SB9: "Solder Bridge ON"
SB2 SB3: "Solder Bridge OFF"
SW1: library part SWITCH_4WAY, "Quad SPST surface mount switch. 1.27mm pitch. Tinned legs.", Manuf_1=CTS
T1: library part 9013-SOT23_1, "NPN Bipolar Transistor", Manuf_1=NXP
TP1 TP2 TP3 TP4 TP5 TP6 TP7 TP8 TP9 TP13 TP14 TP15 TP18 TP19 TP29 TP30 TP31: library part "TP 1mm", "Test Point"
TP12 TP16 TP17 TP22 TP23 TP24 TP25 TP26 TP32 TP33 TP34 TP35 TP36 TP37: library part "TP 0.6mm", "Test Point"
TP20 TP21 TP27 TP28: library part "TP 0.3mm", "Test Point"
U1: "Electronic fuse for 5V line, 3.6A max, DFN10(3x3mm)", Manuf_1=STM
U2: "ESD protection 6V1", Manuf_1=STMICROELECTRONICS
U3: "PMIC WFQFN 5.0x6.0x0.8 44L 0.4 pitch", Manuf_1=ST, Manuf_Part_1=STPMU1APQR
U4: "MPU LFBGA18x18 with crypto", Manuf_1=ST, Manuf_Part_1=STM32MP157CAA3
U5: library part eMMC_THGBMNG5D1LBAIL, "eMMC 4GB 153 Balls WFBGA 15nm", Manuf_1=TOSHIBA
U6: "DDR3L, 16 bits, 4Gb, NANYA, 20nm", Manuf_1=NANYA, Manuf_Part_1=NT5CC256M16ER-EK
U7: "DDR3L, 16 bits, 4Gb, NANYA, 20nm", Manuf_1=NANYA
U8: "USB ESD protection", Manuf_1=ST
U9: "Ultra low drop-low noise BiCMOS voltage, regulators low ESR capacitors compatible", Manuf_1=STM
U10: "Medium-density performance line ARM-based 32-bit MCU with 128KB Flash", Manuf_1=STM
X2: library part XTAL_32K_NX2012SA, "Crystal 32.768kHz, 12.5pF, +/-20ppm@25°C; -0.04ppm/°C² ; ESRmax :70Kohm", Manuf_1=NDK, Manuf_Part_1="NX2012SA 32.768kHz EXS00A-MU00528"
X3: library part XTAL_8M_NX3225GD, "Crystal 8Mhz, 8pF, -+50PPM, SMD", Manuf_1=NDK, Manuf_Part_1="NX3225GD 8MHz EXS00A-CG04874"
X6: "Oscillator 24Mhz, +-50ppm, Vcc:3.3V typ (1.62V min), square wave: [0.1Vcc;0.9Vcc], Enable pin", Manuf_1=NDK, Manuf_Part_1="NZ2016SH 24MHz END4869F"

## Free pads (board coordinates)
  round 0.508 on Mech16: 1(18.738,-18.015) 1(67.585,-18.015)

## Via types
v1: diameter 0.4, hole 0.2, Top Layer to Bottom Layer, tented both sides, 771 vias
v2: diameter 0.6, hole 0.3, Top Layer to Bottom Layer, tented both sides, 670 vias
v3: diameter 0.4, hole 0.2, Top Layer to Bottom Layer, 3 vias

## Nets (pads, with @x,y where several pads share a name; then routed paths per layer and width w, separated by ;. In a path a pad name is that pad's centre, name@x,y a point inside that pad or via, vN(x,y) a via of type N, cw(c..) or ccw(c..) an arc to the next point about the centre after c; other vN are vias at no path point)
1V8: CN7.2 CN7.4 R76.2 | length 40.7
  Signal Layer 2 w0.5: v2(82.5,81.75) 81.325,82.925 v2(81.275,82.925) 78.4,82.925 76.95,81.475 76.322,81.475 75.697,82.1 70.75,82.1 65.475,76.825 61.8,76.825 60.45,78.175 60.45,79.75 57.475,82.725 ; 57.475,82.725 57.2,83 v2(56.75,83) 57.225,83.475 v2(57.475,83.475) 57.475,82.725
  Bottom Layer w0.3: CN7.2@81.1,82.25 CN7.2@81.275,82.25 ; v2(81.275,82.925) CN7.2@81.275,82.25 ; CN7.2@81.275,82.25 81.275,81.925 CN7.4@81.1,81.75 v2(82.5,81.75) 82.5,82.125 82.375,82.25 CN7.2@81.275,82.25
  Bottom Layer w0.5: v2(56.75,83) 57,83 v2(57.475,83.475) 57.527,83.527 R76.2@57.527,84.35
2V8: CN8.2 CN8.4 CN8.6 CN8.8 R75.2 | length 65.6
  Signal Layer 2 w0.5: v2(9.669,81.806) 9.55,81.925 v2(9.55,82.7) 12.025,85.175 23.225,85.175 24.85,86.8 29.2,86.8 30.225,85.775 48.244,85.775 48.394,85.925 57.05,85.925 59.025,83.95 v2(59.025,83.5) 58.575,83.05 v2(58.575,82.925)
  Bottom Layer w0.3: 9.669,81.156 9.763,81.25 CN8.6@11.1,81.25 ; 9.669,81.156 v2(9.669,81.806) ; 9.669,81.156 10.075,80.75 CN8.8@11.1,80.75 CN8.6@11.1,81.25 ; v2(9.669,81.806) 9.725,81.75 CN8.4@11.1,81.75 ; v2(9.669,81.806) 9.669,82.581 v2(9.55,82.7) 10.025,82.7 10.475,82.25 CN8.2@11.1,82.25 CN8.4@11.1,81.75 ; CN8.6@11.1,81.25 CN8.4@11.1,81.75
  Bottom Layer w0.5: v2(58.575,82.925) 58.575,83.05 v2(59.025,83.5) v2(59.025,83.5) R75.2@59.027,84.35
3V3: C81.1 C102.2 CN8.1 CN8.3 CN8.5 CN8.7 R3.1 R4.2 R61.1 R62.1 R87.2 R90.1 U3.27 U5.E6 U5.F5 U5.J10 U5.K9 | length 249.5
  Top Layer w0.1: U3.27@49.479,98.736 49.479,100.104 v1(49.5,100.125)
  Top Layer w0.2: U5.E6@57.8,61.625 U5.F5@58.275,61.15 58.75,60.675 v1(58.75,60.65) ; v1(59.275,63.175) 59.3,63.175 U5.J10@59.775,63.65 ; U5.K9@60.275,63.15 60.75,63.625 v1(60.775,63.625)
  Top Layer w0.3: v1(3.575,83.825) v1(4.25,83.825) ; v1@4.275,83.85 v1(4.25,83.825) ; v1(4.9,83.825) v1(4.25,83.825) ; R3.1@13.525,112.775 v2(13.525,113.5) ; R4.2@23.525,112.775 v2(23.525,113.5)
  Top Layer w0.6: v2(33.381,84.356) 33.875,84.356 34.381,84.356 v2(34.4,84.375) 34.875,84.85 v2(34.875,84.95) 34.4,84.95 v2(33.875,84.95) 33.875,84.85 v2(33.381,84.356)
  Signal Layer 2 w0.1: v1(49.5,100.125) 49.5,101.558 49.504,101.554 50.2,102.25 v1(50.2,108.7)
  Signal Layer 2 w0.3: v1@49.496,100.046 49.5,100.05 v1(49.5,100.125)
  Signal Layer 4 w0.3: v1(4.9,83.825) 4.5,83.825 4.375,83.95 2.9,85.425 2.9,92.775 1.325,94.35 1.325,109.875 1.65,110.2 4.85,113.4 13.425,113.4 v2(13.525,113.5) 16.75,113.5 17.925,114.675 22.35,114.675 v2(23.525,113.5) 24,113.5 25.625,115.125 51.493,115.125 51.818,114.8 63.9,114.8 64.775,115.675 70.728,115.675 71.278,115.125 79.375,115.125 82.025,112.475 82.025,103.747 82.95,102.822 82.95,95.044 82.125,94.219 82.125,82.303 81.95,82.128 81.95,81.9 ; v1(58.75,60.65) 59.55,59.85 60.675,59.85 61.925,61.1 61.925,62.475 ; v1(59.275,63.175) 60.325,63.175 v1(60.775,63.625) 61.925,62.475 ; v1(64.125,81.1) 64.35,80.875 64.425,80.8 71.364,80.8 72.339,81.775 73.253,81.775 74.203,80.825 80.35,80.825 81.425,81.9 81.95,81.9 ; 61.925,62.475 62.025,62.575 72.714,62.575 72.989,62.3 74.486,62.3 74.661,62.475 80.625,62.475 80.775,62.325 81.211,62.325 83.9,65.014 83.9,70.425 81.95,72.375 81.95,81.9
  Bottom Layer w0.3: v1(3.575,83.825) v1(4.25,83.825) v1(4.9,83.825) CN8.1@4.9,82.25 CN8.3@4.9,81.75 CN8.5@4.9,81.25 CN8.7@4.9,80.75 ; v2(34.875,84.95) 35.469,84.356 R87.2@36.052,84.356 ; C102.2@57.95,60.35 58.45,60.35 v1(58.75,60.65) ; v1(59.275,63.175) v1@59.3,63.175 ; v1(60.775,63.625) C81.1@61.625,63.625 ; v1(64.125,80.65) v1(64.125,81.1) R90.1@64.125,81.825
  Bottom Layer w0.5: R62.1@51.05,101.1 R61.1@52.475,101.1
  Bottom Layer w0.7: R61.1@52.475,101.1 52.475,102.45 v2(54.45,104.425) v2(55.125,105.1) 55.75,105.725 v2@55.75,105.75
  other v2: 55.775,105.775
3V3_ST_LINK: C61.1 C63.2 C68.2 C69.2 C70.2 C71.2 CN6.1 R56.1 R66.1 R71.1 R92.2 T1.3 U9.5 U10.1 U10.9 U10.24 U10.36 U10.48 | length 19
  Bottom Layer w0.3: R66.1@59.775,91.6 v1(60.5,91.6) C69.2@61.225,91.6 61.375,91.6 61.775,91.2 U10.24@62.725,91.2 ; v1(63.6,78.225) R92.2@63.6,78.95 ; v1(65.325,82.05) C71.2@65.325,82.775 65.325,82.95 65.725,83.35 U10.9@65.725,84.2 ; U10.1@69.725,84.2 v2(70.45,84.2) ; U10.36@69.725,92.7 70.1,92.7 70.4,93 C68.2@70.4,93.975 v2(71.125,93.975) ; U10.48@71.225,85.7 71.775,85.7 72.275,85.2 C70.2@72.625,85.2 v2(73.35,85.2) ; v2(72.7,88.475) R71.1@72.7,89.2 ; R56.1@83.7,106.375 v2(83.7,107.15)
  Bottom Layer w0.5: U9.5@75.225,104.95 C61.1@76.9,104.95 C63.2@78.075,104.95 v2(78.8,104.95) ; v2(78.35,91.3) 79.25,91.3 T1.3@79.275,91.325 v2(79.275,92.575)
ADC118_DAC1: R24.1 U4.V6 | length 21.4
  Top Layer w0.1: v1(22.575,83.375) 23.795,83.375 R24.1@23.8,83.37 ; U4.V6@27.39,66.78 v1@27.779,67.17
  Bottom Layer w0.1: v1(22.575,83.375) 22.575,82.5 24.025,81.05 24.025,73.845 28.95,68.92 28.95,67.83 28.745,67.625 28.24,67.625 v1(27.785,67.17)
ADC119_DAC2: R25.1 U4.U5 | length 22.9
  Top Layer w0.1: v1(26.2,83.375) 27.145,83.375 R25.1@27.15,83.37 ; v1@27.8,67.97 U4.U5@28.19,67.58
  Bottom Layer w0.1: v1(26.2,83.375) 26.2,74.6 25.925,74.325 25.925,72.228 28.851,69.301 29.399,69.301 29.735,68.965 29.735,68.625 29.53,68.42 29.42,68.42 29.15,68.15 29.15,67.747 28.828,67.425 28.425,67.425 28.135,67.135 28.135,67.025 27.9,66.79 27.66,66.79 27.35,67.1 27.35,67.525 v1(27.8,67.975)
AIN_1: R90.2 R91.2 U10.10 | length 3.2
  Bottom Layer w0.2: R91.2@63.05,82.725 R90.2@64.125,82.725 64.675,83.275 64.975,83.275 65.225,83.525 U10.10@65.225,84.2
ANA0: R22.1 U4.R4 | length 31.3
  Top Layer w0.09: v1(15.075,80.025) 17.045,80.025 17.25,80.23 17.611,80.23 18.091,80.71 27.352,80.71 28.921,80.71 29.29,80.341 29.29,78.962 29.44,78.812 29.44,75.509 29.248,75.316 29.248,74.773 30.095,73.925 30.095,68.685 U4.R4@29.79,68.38 ; v1(15.075,83.375) R22.1@15.8,83.375
  Bottom Layer w0.1: v1(15.075,80.025) v1(15.075,83.375)
ANA0_MB: CN8.10 SB6.2 | length 9.8
  Top Layer w0.1: v1(12.075,87.5) 12.475,87.9 13.5,87.9
  Bottom Layer w0.1: CN8.10@11.1,80.25 11.95,80.25 12.1,80.4 12.1,87.475 v1(12.075,87.5)
ANA1: R23.1 U4.T5 | length 19.9
  Top Layer w0.1: R23.1@20.425,83.375 v1(21.35,83.375) ; v1@28.6,67.97 U4.T5@28.99,67.58
  Bottom Layer w0.1: v1(21.35,83.375) 23.825,80.9 23.825,73.762 28.2,69.387 28.2,68.375 v1(28.6,67.975)
ANA1_MB: CN8.12 SB7.2 | length 14.4
  Top Layer w0.1: v1(17.3,87.2) 17.3,87.75 17.55,88 17.75,88
  Signal Layer 2 w0.1: v1(12.525,87.2) v1(17.3,87.2)
  Bottom Layer w0.1: CN8.12@11.1,79.75 11.9,79.75 12.3,80.15 12.3,86.95 12.525,87.175 v1(12.525,87.2)
ANTI_TAMP2: CN8.29 TP6.1 U4.N1 | length 46.1
  Top Layer w0.1: v1(3.3,75.279) 3.321,75.3 4.475,75.3 4.812,75.637 6.7,77.525 8.15,77.525 11.35,80.725 17.562,80.725 17.932,81.095 29.405,81.095 30.1,80.4 33.986,80.4 34.475,79.911 34.475,75.245 31.39,72.16 U4.N1@31.39,70.78
  Bottom Layer w0.1: v1(3.3,75.279) 3.329,75.25 CN8.29@4.9,75.25
BOOT0: CN3.2 SW1.8 U4.N3 | length 63.3
  Top Layer w0.09: SW1.8@14.825,94.725 14.853,94.753 v1(15.825,94.753) ; U4.N3@31.39,69.18 31.39,69.548 31.695,69.853 31.695,72.189 34.67,75.164 34.67,80.086 34.156,80.6 33.9,80.6
  Top Layer w0.1: v1(15.576,81.079) 15.58,81.075 17.209,81.075 17.443,81.309 29.491,81.309 30.2,80.6 33.9,80.6
  Signal Layer 2 w0.1: v1(15.825,94.753) 19.072,98 21.255,98 21.845,98.59 21.845,100.655 21.5,101 21.5,101.643 21.845,101.988 21.845,103.84 CN3.2@20.67,105.015
  Bottom Layer w0.1: v1@15.575,81.05 v1@15.575,81.079 ; v1@15.576,81.051 v1(15.576,81.079) 15.576,81.801 16.275,82.5 16.275,85.411 17.85,86.986 17.85,91.55 15.825,93.575 v1(15.825,94.753)
BOOT1: CN3.4 SW1.7 U4.N4 | length 60.7
  Top Layer w0.09: SW1.7@13.555,94.725 13.555,95.555 13.725,95.725 v1(15.825,95.725) ; v1(16,81.425) 16.11,81.535 29.565,81.535 30.269,80.831 33.964,80.831 ; U4.N4@31.39,68.38 31.39,68.748 31.885,69.243 31.885,72.11 34.86,75.085 34.86,80.252 34.282,80.83 33.964,80.83
  Signal Layer 2 w0.1: v1(15.825,95.725) 19.4,99.3 19.4,101.205 CN3.4@20.67,102.475
  Bottom Layer w0.1: v1(15.825,95.725) 16.3,95.25 16.3,93.45 18.05,91.7 18.05,85.533 16.475,83.958 16.475,81.9 v1(16,81.425)
BOOT2: CN3.6 SW1.6 U4.P4 | length 55.8
  Top Layer w0.09: v1(12.3,93.6) 12.285,93.615 SW1.6@12.285,94.725 12.285,95.885 13.2,96.8 19.6,96.8 20.7,97.9 20.67,97.93 CN3.6@20.67,99.935 ; v1(14.45,80.375) 14.495,80.42 17.533,80.42 18.013,80.9 27.431,80.9 29,80.9 29.48,80.42 29.48,79.041 29.63,78.891 29.63,75.43 29.438,75.238 29.438,74.851 30.285,74.004 30.285,68.685 U4.P4@30.59,68.38
  Bottom Layer w0.1: v1(12.3,93.6) 13.65,92.25 13.65,87.1 14.45,86.3 v1(14.45,80.375)
BST_OUT: C12.2 U3.34 U3.37 | length 10.3
  Top Layer w0.2: C12.2@43.7,99.825 43.875,100 44.577,100 44.825,100 45.31,99.515 45.325,99.5 45.325,99.475 45.848,98.952 46.064,98.736 U3.34@46.679,98.736 ; 44.545,97.286 U3.37@45.929,97.286
  Top Layer w0.3: v2@43.388,97.236 v2(43.518,97.106) ; v2@44.052,97.106 v2(44.124,97.106) ; v2@44.124,97.034 44.209,96.949 44.245,96.985 44.545,97.286
  Top Layer w0.4: v2@44.232,97.286 44.545,97.286
  Top Layer w0.6: v2(42.852,97.106) v2(43.518,97.106) v2@44.052,97.106
  Signal Layer 4 w0.2: v2@42.775,97.125 42.823,97.077 42.825,97.075 42.852,97.075 43.518,97.075 v2@43.971,97.075 ; v2(44.577,99.956) 44.894,99.956 45.323,99.527 45.873,98.977 45.875,98.975 45.875,98.956 v2@45.875,98.95
  other v2: 45.852,98.956 45.302,99.506
CAN1_RX: CN7.97 U4.J5 | length 63.2
  Top Layer w0.1: v1@34.2,67.19 U4.J5@34.59,67.58 ; v1(68.425,68.625) 68.425,68.618 70.098,66.945 74.245,66.945 v1(74.25,66.95)
  Signal Layer 2 w0.1: v1(34.195,67.19) 34.195,67.495 33.845,67.845 33.845,68.395 33.95,68.5 33.95,68.503 36.147,70.7 39.143,70.7 40.143,69.7 65.058,69.7 66.458,68.3 68.1,68.3 v1(68.425,68.625)
  Signal Layer 3 w0.1: v1(74.25,66.95) 75.075,66.125 75.075,60.017 76.15,58.942 76.15,57.172 77.8,55.522 77.8,54.695 77,53.895 77,53.6 v1(77.35,53.25)
  Bottom Layer w0.1: CN7.97@74.9,53.25 v1(77.35,53.25)
CAN1_TX: CN7.95 U4.D3 | length 69.6
  Top Layer w0.09: U4.D3@38.59,69.18 38.59,69.548 38.285,69.853 38.285,70.133 38.627,70.475 38.716,70.475 38.895,70.653 38.895,71.222 40.655,72.982 40.655,74.051 42.179,75.575 42.454,75.85 42.7,75.85
  Top Layer w0.1: 42.7,75.85 62.55,75.85 62.925,76.225 71.919,76.225 72.294,75.85 73.351,75.85 73.651,76.15 75.245,76.15 76.17,75.225 76.575,75.225 v1(76.579,75.229)
  Signal Layer 2 w0.1: v1(76.579,75.229) v1@76.654,75.229
  Signal Layer 3 w0.1: v1(76.579,75.229) 76.75,75.057 76.75,71.775 76.55,71.575 76.55,63.55 76.75,63.35 76.75,62.47 76.45,62.17 76.45,61.103 78,59.553 78,58.395 77,57.395 77,56.605 78,55.605 78,54.4 v1(77.35,53.75)
  Bottom Layer w0.1: CN7.95@74.9,53.75 v1(77.35,53.75)
CAN_FD_STBY: CN8.39 U4.U4 | length 26.7
  Top Layer w0.1: U4.U4@28.19,68.38 v1@28.58,68.77
  Signal Layer 2 w0.1: v1(6,72.75) 6.45,73.2 11.775,73.2 12.225,72.75 12.85,72.75 13.384,73.284 18.309,73.284 18.917,72.675 20.708,72.675 21.758,71.625 25.212,71.625 26.762,70.075 27.28,70.075 v1(28.585,68.77)
  Bottom Layer w0.1: CN8.39@4.9,72.75 v1(6,72.75)
CLK_SD: CN9.5 M1.17 | length 6
  Top Layer w0.1: M1.17@66.925,8.125 v1(71.675,8.125)
  Bottom Layer w0.13: CN9.5@70.4,8.125 v1(71.675,8.125)
CMD_SD: CN9.3 M1.14 R115.1 | length 10.2
  Top Layer w0.2: M1.14@66.925,5.125 66.925,4.275 67.275,3.925 v3(67.475,3.925)
  Signal Layer 3 w0.2: v3(67.475,3.925) 68.65,5.1 v1(68.65,9.65)
  Bottom Layer w0.2: v1(68.65,9.65) R115.1@68.65,10.325 CN9.3@70.4,10.325
DATA0_SD: CN9.7 M1.15 R121.1 | length 7.9
  Top Layer w0.13: M1.15@66.925,6.125 67.125,5.925 v1(71.675,5.925)
  Bottom Layer w0.13: R121.1@68.65,5.925 CN9.7@70.4,5.925 v1(71.675,5.925)
DATA1_SD: CN9.8 M1.13 R135.1 | length 10.1
  Top Layer w0.13: M1.13@65.775,4.475 66.975,3.275 70.125,3.275 v1(71.675,4.825)
  Bottom Layer w0.13: R135.1@68.65,4.825 CN9.8@70.4,4.825 v1(71.675,4.825)
DATA2_SD: CN9.1 M1.19 R111.1 | length 8.8
  Top Layer w0.1: M1.19@66.925,10.125 67.65,10.125 70.05,12.525 v1(71.675,12.525)
  Bottom Layer w0.13: R111.1@68.65,12.525 CN9.1@70.4,12.525 v1(71.675,12.525)
DATA3_SD: CN9.2 M1.18 R113.1 | length 8.7
  Top Layer w0.1: M1.18@66.925,9.125 67.375,9.125 69.675,11.425 v1(71.675,11.425)
  Bottom Layer w0.13: R113.1@68.65,11.425 CN9.2@70.4,11.425 v1(71.675,11.425)
DCMI_D0: CN7.68 U4.E6 | length 50.7
  Top Layer w0.1: v1@37.4,67.17 U4.E6@37.79,66.78
  Signal Layer 2 w0.1: v1(37.4,67.175) 37.4,66.975 37.8,66.575 37.8,66.175 38.125,65.85 39.55,65.85 39.925,65.475 63.475,65.475 64.6,64.35 80.425,64.35 80.625,64.55 v1(80.625,64.6)
  Signal Layer 3 w0.1: v1(80.05,60.75) 80.4,61.1 80.4,61.895 80.25,62.045 80.25,64.225 v1(80.625,64.6)
  Bottom Layer w0.1: v1(80.05,60.75) CN7.68@81.1,60.75
DCMI_D1: CN7.71 U4.B1 | length 55.2
  Top Layer w0.09: U4.B1@40.19,70.78 41.605,72.195 41.605,73.629 42.389,74.412 43.15,74.412 ; 64.199,75.225 64.6,75.225
  Top Layer w0.1: 43.15,74.412 63.379,74.412 64.192,75.225 64.199,75.225 ; 64.6,75.225 71.134,75.225 72.409,73.95 74.45,73.95 v1(75.975,72.425)
  Signal Layer 3 w0.09: 75.83,66.805 75.83,60.595 76.675,59.75 v1(77.025,59.75)
  Signal Layer 3 w0.1: 75.83,66.805 75.83,72.28 v1(75.975,72.425)
  Bottom Layer w0.09: CN7.71@74.9,59.75 v1(77.025,59.75)
DCMI_D2: CN7.73 U4.B3 | length 55.6
  Top Layer w0.09: U4.B3@40.19,69.18 40.495,69.485 40.495,70.816 41.795,72.116 41.795,73.55 42.457,74.212 43.15,74.212
  Top Layer w0.1: 43.15,74.212 63.462,74.212 64.275,75.025 71.051,75.025 72.326,73.75 73.425,73.75 v1(73.775,73.4)
  Signal Layer 3 w0.1: v1(73.775,73.4) 74.025,73.4 75.63,71.795 75.63,66.722 75.635,66.717 75.635,60.315 v1(76.7,59.25)
  Bottom Layer w0.1: CN7.73@74.9,59.25 v1(76.7,59.25)
DCMI_D3: CN7.64 U4.F5 | length 49.4
  Top Layer w0.1: U4.F5@36.99,67.58 v1@37.38,67.97
  Signal Layer 2 w0.1: v1(37.385,67.97) 38.207,67.97 38.635,67.542 38.635,67.025 38.885,66.775 39.7,66.775 40.375,66.1 63.9,66.1 65.05,64.95 79.75,64.95 v1(80.05,65.25)
  Signal Layer 3 w0.1: v1(80.05,61.75) v1(80.05,65.25)
  Bottom Layer w0.1: v1(80.05,61.75) CN7.64@81.1,61.75
DCMI_D4: CN7.61 U4.C2 | length 53.7
  Top Layer w0.09: U4.C2@39.39,69.98 39.39,70.348 39.695,70.653 39.695,71.101 41.225,72.631 41.225,73.786 42.489,75.05 42.825,75.05
  Top Layer w0.1: 42.825,75.05 63.025,75.05 63.6,75.625 71.3,75.625 72.575,74.35 75.292,74.35 75.842,73.8 75.85,73.8 76.2,73.45 v1(76.2,73.2)
  Signal Layer 3 w0.1: v1(76.175,62.975) 76.055,63.095 76.055,71.905 76.275,72.125 76.275,72.128 76.325,72.178 76.325,73.075 v1(76.2,73.2)
  Bottom Layer w0.1: CN7.61@74.9,62.25 75.92,62.25 76.175,62.505 v1(76.175,62.975)
DCMI_D5: CN7.66 U4.J6 | length 61.4
  Top Layer w0.12: v1(34.19,66.38) U4.J6@34.59,66.78
  Signal Layer 2 w0.1: v1(34.19,66.38) 34.19,66.69 34.65,67.151 34.65,68.12 34.855,68.325 35.049,68.325 35.399,68.675 35.399,69.049 36.55,70.2 38.825,70.2 39.875,69.15 64.55,69.15 66.025,67.675 70.255,67.675 71.855,69.275 72.8,69.275 73.95,68.125 79.65,68.125 80.847,66.928 v1(81.854,66.928)
  Signal Layer 3 w0.1: v1(81.854,66.928) 82.525,66.257 82.525,61.582 v1(82.904,61.203)
  Bottom Layer w0.1: CN7.66@81.1,61.25 82.857,61.25 v1(82.904,61.203)
DCMI_D6: CN7.69 U4.AB8 | length 59.8
  Top Layer w0.09: v1(23.376,65.128) 23.376,65.151 v1@23.405,65.18
  Top Layer w0.1: v1@23.405,65.18 U4.AB8@24.19,65.18
  Signal Layer 2 w0.09: v1(23.376,65.128) v1@23.376,65.199 ; 27.15,64.595 27.62,64.595 28.38,65.355 28.38,66.379 28.731,66.73 29.645,66.73 30.545,65.83 30.806,65.83 30.811,65.835 32.364,65.835 32.519,65.68 35.72,65.68 36.05,65.35 36.05,62.899 36.675,62.275 37.5,62.275 37.75,62.025 39.125,62.025 39.625,62.525 53.401,62.525 54.813,61.113 55.282,61.113 56.5,59.895 61.505,59.895 62.605,60.995 63.23,60.995 63.955,60.27 73.73,60.27 v1(73.75,60.25)
  Signal Layer 2 w0.1: v1(23.376,65.128) 25.041,65.128 25.82,64.35 26.45,64.35 26.69,64.59 27.15,64.59
  Bottom Layer w0.1: v1(73.75,60.25) CN7.69@74.9,60.25
DCMI_D7: CN7.72 U4.E9 | length 47.7
  Top Layer w0.1: U4.E9@37.79,64.38 v1@38.179,64.77
  Signal Layer 2 w0.1: v1(38.185,64.77) 38.745,65.33 39.218,65.33 39.673,64.875 60.525,64.875 61.375,64.025 63.925,64.025 64.288,63.662 78.588,63.662 78.75,63.5 v1(78.75,63.475)
  Signal Layer 3 w0.1: v1(78.75,63.475) 79.45,62.775 79.45,59.975 79.675,59.75 v1(80.075,59.75)
  Bottom Layer w0.1: v1(80.075,59.75) CN7.72@81.1,59.75
DCMI_D8: CN7.62 U4.E2 | length 70.5
  Top Layer w0.09: U4.E2@37.79,69.98 38.285,70.475 38.285,71.15 40.275,73.14 40.275,74.244 40.645,74.614 40.652,74.614 42.664,76.625 42.671,76.625
  Top Layer w0.1: 42.671,76.625 42.771,76.725 71.984,76.725 72.459,76.25 73.186,76.25 73.761,76.825 75.5,76.825 76.15,76.175 76.15,76.005 76.355,75.8 76.85,75.8 78.45,77.4 79.645,77.4 79.845,77.6 v1(83.975,77.6)
  Signal Layer 3 w0.1: v1(83.975,77.6) 84.45,77.125 84.45,62.575 84.45,62.424 v1(84.279,62.253)
  Bottom Layer w0.1: CN7.62@81.1,62.25 84.276,62.25 v1(84.279,62.253)
DCMI_D9: CN7.65 U4.W2 | length 103.2
  Top Layer w0.09: 25.425,71.845 25.51,71.76 26.285,70.985 26.285,70.285 U4.W2@26.59,69.98
  Top Layer w0.1: v1(19.25,73.6) 20.3,72.55 20.65,72.55 21.575,71.625 22.85,71.625 23.125,71.9 25.362,71.9 25.421,71.841 ; v1(19.55,83.225) 20.15,82.625 36.475,82.625 37.75,81.35 60.275,81.35 62.3,83.375 75.025,83.375 75.775,82.625 v1(76.8,82.625)
  Signal Layer 3 w0.1: v1(76.8,82.625) 77.235,82.19 77.235,80.915 77.75,80.4 77.75,73.65 78.1,73.3 78.1,62 v1(77.35,61.25)
  Bottom Layer w0.1: v1(19.25,73.6) 19.675,74.025 19.675,83.1 v1(19.55,83.225) ; CN7.65@74.9,61.25 v1(77.35,61.25)
DCMI_D10: CN7.63 U4.E3 | length 62.3
  Top Layer w0.09: U4.E3@37.79,69.18 37.485,69.485 37.485,70.285 37.675,70.475 37.916,70.475 38.095,70.653 38.095,71.228 40.085,73.218 40.085,74.322 40.571,74.809
  Top Layer w0.1: 40.571,74.809 42.688,76.925 72.067,76.925 72.542,76.45 73.103,76.45 73.678,77.025 75.625,77.025 v1(76.5,76.15)
  Signal Layer 3 w0.1: v1(76.5,76.15) 76.95,75.7 76.95,62.23 ; v1(76.8,62.025) 76.955,62.18 76.955,63.325
  Bottom Layer w0.1: CN7.63@74.9,61.75 76.525,61.75 v1(76.8,62.025)
DCMI_D11: CN7.75 U4.C1 | length 59.7
  Top Layer w0.09: U4.C1@39.39,70.78 39.39,71.065 41.035,72.71 41.035,73.865 41.825,74.655 42.415,75.245 42.737,75.245
  Top Layer w0.1: 42.737,75.245 42.742,75.25 62.942,75.25 63.517,75.825 71.753,75.825 72.478,75.1 72.92,75.1 73.12,74.9 75.025,74.9 75.925,74 v1(76.3,74)
  Signal Layer 3 w0.09: v1(76.3,74) 76.3,73.588 76.545,73.343 76.545,72.119 76.25,71.824 76.25,63.388 76.52,63.118 76.52,62.832 76.02,62.332 76.02,60.674 76.599,60.095 77.168,60.095 77.37,59.893 77.37,59.607 77.254,59.491 v1(77.254,58.753)
  Bottom Layer w0.09: CN7.75@74.9,58.75 77.251,58.75 v1(77.254,58.753)
DCMI_HSYNC: CN7.70 U4.D6 | length 49.6
  Top Layer w0.1: U4.D6@38.59,66.78 v1@38.98,67.17
  Signal Layer 2 w0.1: v1(38.985,67.17) 39.18,66.975 39.783,66.975 40.458,66.3 63.983,66.3 65.133,65.15 79.275,65.15 v1(79.925,65.8)
  Signal Layer 3 w0.1: v1(79.925,65.8) 79.7,65.575 79.7,60.375 79.825,60.25 v1(80.05,60.25)
  Bottom Layer w0.1: v1(80.05,60.25) CN7.70@81.1,60.25
DCMI_PIXCK: CN7.67 U4.W9 | length 53.8
  Top Layer w0.1: U4.W9@26.59,64.38 v1@26.98,63.99
  Signal Layer 2 w0.1: v1(26.98,63.985) 27.345,64.35 27.675,64.35 27.675,64.374 28.575,65.274 28.575,65.6 28.855,65.88 29.945,65.88 30.4,65.425 34.15,65.425 34.74,64.835 34.74,63.335 35.645,62.43 36.22,62.43 36.6,62.05 37.449,62.05 37.67,61.83 39.24,61.83 39.735,62.325 53.325,62.325 54.8,60.85 55.25,60.85 56.4,59.7 72.675,59.7 72.913,59.938 72.925,59.95 v1(72.925,59.925)
  Bottom Layer w0.1: v1(72.925,59.925) 73.75,60.75 CN7.67@74.9,60.75
DCMI_VSYNC: CN7.74 U4.F11 | length 50
  Top Layer w0.1: v1@36.6,63.17 U4.F11@36.99,62.78
  Signal Layer 2 w0.1: v1(36.6,63.175) 36.905,63.175 37.255,62.825 37.545,62.825 37.695,62.975 54.85,62.975 57.1,60.725 58.33,60.725 58.605,61 61.375,61 62,61.625 63.6,61.625 64.175,61.05 75.275,61.05 76.625,62.4 78.65,62.4 79.125,61.925 79.125,59.725 79.6,59.25 v1(80.075,59.25)
  Bottom Layer w0.1: v1(80.075,59.25) CN7.74@81.1,59.25
DDR_A0: R128.1 U4.K19 U6.N3 U7.N3 | length 77.8
  Top Layer w0.12: U6.N3@29.39,35.78 v1(29.79,35.38) ; U7.N3@31.64,15.92 v1(32.04,15.52) ; U4.K19@33.79,56.38 v1(34.19,56.78)
  Bottom Layer w0.12: R128.1@31.82,5.77 31.82,6.71 32.11,7 32.11,8.95 33.43,10.27 33.43,11.7 33.97,12.24 33.97,14.22 33.07,15.12 32.65,15.12 32.269,15.501 v1@32.04,15.501 ; v1@32.039,15.501 32.03,15.51 31.46,16.08 31.46,22.48 31.02,22.92 31.02,31.961 31.44,32.381 31.44,34.25 30.67,35.02 30.4,35.02 30.04,35.38 v1(29.79,35.38) 29.571,35.38 29.21,35.741 29.21,36.42 29.38,36.59 29.38,40.615 30.225,41.46 43.316,41.46 44.19,42.334 44.19,44.672 43.42,45.442 43.42,47.275 43.76,47.615 43.76,48.93 43.64,49.05 40.792,49.05 39.73,50.112 39.73,51.95 39.4,52.28 38.306,52.28 37.486,53.1 36.778,53.1 34.6,55.278 34.6,56.079 34.19,56.489 v1(34.19,56.78)
DDR_A1: R116.1 U4.M18 U6.P7 U7.P7 | length 76.2
  Top Layer w0.12: v1(25.79,36.18) U6.P7@26.19,36.58 ; v1(28.04,16.32) U7.P7@28.44,16.72 ; U4.M18@32.19,57.18 v1(32.59,57.58)
  Bottom Layer w0.12: R116.1@24.09,10.09 25.13,10.09 27.1,12.06 27.1,13.81 27.63,14.34 27.63,15.866 28.04,16.276 v1(28.04,16.32) 28.397,16.677 28.397,19.593 26.594,21.396 26.594,25.767 26.17,26.191 26.17,27.02 25.79,27.4 25.79,27.64 26.16,28.01 26.17,28.01 26.17,30.2 25.78,30.59 25.15,30.59 24.99,30.75 24.99,34.07 25.35,34.43 25.35,34.58 25.42,34.65 25.43,34.65 25.43,35.529 25.781,35.88 25.79,35.88 v1(25.79,36.18) 26.19,36.58 26.19,40.318 26.019,40.488 26.019,41.057 25.849,41.227 25.849,41.841 25.55,42.14 24.92,42.14 24.8,42.26 24.8,42.45 24.93,42.58 25.55,42.58 25.849,42.879 25.849,43.915 28.634,46.7 28.89,46.7 29.3,46.29 30.57,46.29 30.77,46.49 30.77,47.1 30.57,47.3 30.26,47.3 30.05,47.09 30.05,46.85 29.91,46.71 29.71,46.71 29.58,46.84 29.58,47.07 29.35,47.3 26.54,47.3 26.03,47.3 25.94,47.39 25.94,47.65 26.01,47.72 28.25,47.72 28.89,48.36 28.89,48.828 29.512,49.45 29.98,49.45 30.13,49.6 30.13,49.9 29.79,50.24 26.77,50.24 26.61,50.4 26.61,50.74 26.7,50.83 29.64,50.83 30.14,51.33 30.14,55.421 31.35,56.631 31.35,56.849 31.681,57.18 32.19,57.18 v1(32.59,57.58)
DDR_A2: R126.1 TP32.1 U4.J18 U6.P3 U7.P3 | length 79.8
  Top Layer w0.12: U6.P3@29.39,36.58 v1(29.79,36.18) ; U7.P3@31.64,16.72 v1(32.04,16.32) ; U4.J18@34.59,57.18 v1(34.99,56.78)
  Bottom Layer w0.12: v1(29.79,36.18) 30.04,36.18 30.48,35.74 30.739,35.74 31.18,35.299 31.18,35.281 31.391,35.07 31.409,35.07 32.675,33.805 TP32.1@32.74,33.739 ; v1@29.833,36.2 29.833,39.88 30.573,40.62 43.664,40.62 45.03,41.986 45.03,45.02 44.27,45.78 44.27,46.937 44.97,47.637 44.97,48.076 44.6,48.446 44.6,49.124 44.81,49.334 44.81,49.748 44.658,49.9 41.27,49.9 40.57,50.6 40.57,52.78 40.23,53.12 38.654,53.12 37.834,53.94 37.126,53.94 35.41,55.656 35.41,56.36 v1(34.99,56.78) ; TP32.1@32.5,33.63 32.631,33.63 TP32.1@32.74,33.739 ; R126.1@34.03,5.77 35.37,7.11 35.37,9.99 35.15,10.21 35.15,14.159 34.555,14.754 34.555,15.244 34.319,15.48 33.57,15.48 33.13,15.92 32.731,15.92 32.331,16.32 v1(32.04,16.32) 32.04,20.03 32.74,20.73 32.74,33.63 TP32.1@32.74,33.739
DDR_A3: R127.1 U4.J19 U6.N2 U7.N2 | length 77.1
  Top Layer w0.12: U6.N2@30.19,35.78 v1(30.59,35.38) ; U7.N2@32.44,15.92 v1(32.84,15.52) ; U4.J19@34.59,56.38 v1(34.99,55.98)
  Bottom Layer w0.12: R127.1@32.87,5.77 32.53,6.11 32.53,7.97 33.24,8.68 33.24,9.51 33.62,9.89 33.869,9.89 34.24,10.261 34.24,14.42 33.14,15.52 v1(32.84,15.52) 32.561,15.52 32.171,15.91 31.941,15.91 31.68,16.171 31.68,23.45 31.28,23.85 31.28,31.91 31.71,32.34 31.71,34.291 30.621,35.38 v1(30.59,35.38) 30.351,35.38 29.941,35.79 29.671,35.79 29.43,36.031 29.43,36.329 29.6,36.499 29.6,40.241 30.399,41.04 43.49,41.04 44.61,42.16 44.61,44.846 43.84,45.616 43.84,47.101 44.18,47.441 44.18,49.24 43.95,49.47 40.966,49.47 40.15,50.286 40.15,52.16 39.61,52.7 38.48,52.7 37.66,53.52 36.952,53.52 35.616,54.856 35.614,54.856 34.99,55.48 v1(34.99,55.98)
